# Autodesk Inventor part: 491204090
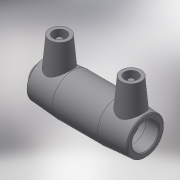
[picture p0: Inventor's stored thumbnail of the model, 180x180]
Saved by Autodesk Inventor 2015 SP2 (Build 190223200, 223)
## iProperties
Created: 2017-06
Part Number: 491204090
Material: Generic
Description: PLASSON END CAP 90
Document SubType Name: Modeling
Designer: KIM
Mass: 38.9236 g
Surface Area: 152.394 cm^2
Volume: 38.9236 cm^3
Density: 1 g/cm^3
Appearance: Default
Author: KIM
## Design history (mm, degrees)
derived "491204.ipt"
feature "Solid1::491204.ipt"
tag "TaggingFeature1"
body "Solid1"
other parameters: "d0" = 148, "d2" = 117, "d3" = 73, "d4" = 45.75, "d5" = 105.3, "d6" = 85.5, "d8" = 168 deg, "d10" = 29.2, "d11" = 9.73333, "d13" = 146.4, "d14" = 17.6296, "d15" = 73, "d16" = 73, "d17" = 85.5, "d19" = 3.52592, "d20" = 168 deg, "d22" = 109.98, "d23" = 117, "d24" = 106.6806, "d25" = 135 deg, "d26" = 65.88, "d27" = 135 deg, "d30" = 15, "d31" = 58.56, "d34" = 5 deg, "d35" = 15, "d39" = 5 deg, "d41" = 4, "d42" = 14, "d43" = 0, "d45" = 4, "d46" = 14, "d47" = 0, "d48" = 183, "d49" = 1, "d51" = 72, "d52" = 3.294, "d53" = 99, "d54" = 3.294, "d56" = 9, "d57" = 2.7, "d60" = 27.45, "d61" = 1.8, "d63" = 183, "d64" = 1, "d66" = 72, "d67" = 18, "d68" = 99, "d69" = 3.66, "d70" = 0, "d71" = 3.294, "d72" = 3, "d73" = 0, "d74" = 21.17, "d75" = 7.05667, "d76" = 3, "d77" = 0, "L_" = 183, "L_1" = 73, "D_" = 117, "d_2" = 12, "L_0" = 148, "d55" = 9
